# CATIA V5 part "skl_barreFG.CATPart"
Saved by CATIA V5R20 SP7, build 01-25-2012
Part number: skl_barreFG
Publications: "Axe pivot FG/EF", "Axe pivot FG/AB", "Plan FG"
Bounding box of the stored display mesh (mm): x 0 to 0, y -16.233 to 12.798, z 18.679 to 40.06
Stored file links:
  U:\IAO_bon\skl_barreFG.CATPart
  U:\IAO_bon\skl_IAO.CATProduct
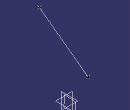
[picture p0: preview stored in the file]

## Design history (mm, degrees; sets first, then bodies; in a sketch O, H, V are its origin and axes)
Set1
  Point1 "Point F": linked copy from another document
  Point2 "Point B/G": linked copy from another document
  Plane1 "Plan Ref": linked copy from another document
Set2
  Line1: type PtPt, FirstPoint Point1, SecondPoint Point2
  Line2 "Axe pivot FG/EF": type Normal, RefPoint Point1, RefSkin Plane1, Start 0, End 20
  Line3 "Axe pivot FG/AB": type Normal, RefPoint Point2, RefSkin Plane1, Start 0, End 20
  Plane2 "Plan FG": type Normal, Curve Line3, RefPoint Point2
  Line4 "Axe pivot FG/BC": type Normal, RefPoint Point2, RefSkin Plane2, Start 0, End 20
Body1 (main body)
